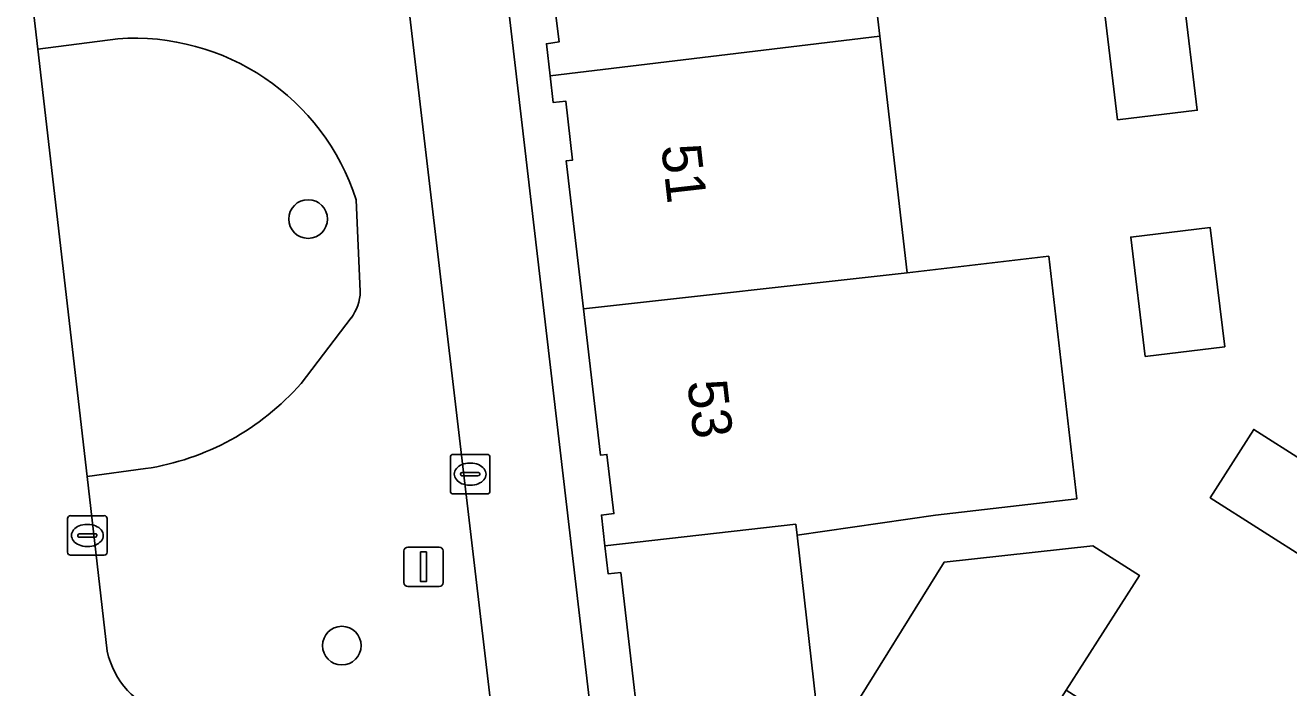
# Model space of a CAD drawing. Extents: x 160377 to 161131, y 383938 to 384853.
# Drawn here: x 160622.12 to 160654.07, y 384704.66 to 384721.42 of the extents above; entities that cross this region are included whole.
import ezdxf

# ---------------------------------------------------------------- set-up
doc = ezdxf.new("R2010")
doc.units = 0
for name, color, linetype in [('IMGEO_Boom', 7, 'Continuous'), ('IMGEO_Erf', 7, 'Continuous'), ('IMGEO_Groenvoorziening', 7, 'Continuous'), ('IMGEO_Kolk', 7, 'Continuous'), ('IMGEO_Lichtmast', 7, 'Continuous'), ('IMGEO_Pand', 7, 'Continuous'), ('IMGEO_Pand_nummerreeks', 7, 'Continuous'), ('IMGEO_Voetpad_open', 7, 'Continuous')]:
    doc.layers.add(name, color=color, linetype=linetype)

msp = doc.modelspace()

# ---------------------------------------------------------------- linework, layer by layer
at = {"layer": 'IMGEO_Boom'}
for centre in [(160629.273, 384716.516), (160630.125, 384705.727)]:
    msp.add_circle(centre, 0.489, dxfattribs=at)
at = {"layer": 'IMGEO_Erf'}
for points in [[(160632.299, 384739.297), (160636.778, 384701.013), (160651.295, 384691.787), (160664.092, 384683.65)], [(160643.028, 384727.125), (160643.724, 384721.143), (160644.42, 384715.158), (160647.997, 384715.574), (160648.71, 384709.441), (160645.133, 384709.025), (160641.634, 384708.517), (160642.115, 384704.265), (160642.853, 384703.807), (160645.353, 384707.836), (160649.116, 384708.253), (160650.289, 384707.505), (160648.439, 384704.604), (160653.696, 384701.251), (160658.7, 384698.06)], [(160637.881, 384701.541), (160637.177, 384707.576), (160636.86, 384707.539), (160636.777, 384708.248), (160636.686, 384709.028), (160637.003, 384709.065), (160636.828, 384710.561), (160636.669, 384710.542), (160636.236, 384714.242), (160635.798, 384717.99), (160635.957, 384718.008), (160635.789, 384719.496), (160635.471, 384719.46), (160635.393, 384720.133), (160635.299, 384720.95), (160635.618, 384720.995), (160635.436, 384722.483)]]:
    msp.add_lwpolyline(points, dxfattribs=at)
for points in [[(160651.751, 384719.266), (160649.737, 384719.026), (160649.375, 384722.054), (160651.39, 384722.295)], [(160652.448, 384713.287), (160650.439, 384713.042), (160650.07, 384716.058), (160652.079, 384716.303)], [(160654.625, 384707.845), (160652.082, 384709.466), (160653.183, 384711.194), (160655.726, 384709.574)]]:
    msp.add_lwpolyline(points, close=True, dxfattribs=at)
at = {"layer": 'IMGEO_Groenvoorziening'}
for points in [[(160633.874, 384704.387), (160629.795, 384739.039), (160624.35, 384738.394)], [(160624.908, 384727.058), (160621.946, 384725.035), (160622.435, 384720.808), (160624.459, 384721.074)], [(160624.459, 384721.074), (160622.435, 384720.808)], [(160622.435, 384720.808), (160623.683, 384710.004), (160625.159, 384710.204)], [(160630.592, 384714.684), (160630.487, 384717.005)], [(160630.487, 384717.005), (160630.592, 384714.684)], [(160629.094, 384712.359), (160630.357, 384714.013)], [(160630.357, 384714.013), (160629.094, 384712.359)], [(160625.159, 384710.204), (160623.683, 384710.004), (160624.193, 384705.586)]]:
    msp.add_lwpolyline(points, dxfattribs=at)
for centre, radius, start, end in [((160624.877, 384715.194), 5.895, 17.8911, 94.0689), ((160624.877, 384715.194), 5.895, 17.8911, 94.0689), ((160629.39, 384714.728), 1.203, 323.5082, 357.8889), ((160629.39, 384714.728), 1.203, 323.5082, 357.8889), ((160624.189, 384716.645), 6.514, 278.5642, 318.8504), ((160624.189, 384716.645), 6.514, 278.5642, 318.8504), ((160626.288, 384706.042), 2.144, 192.2828, 252.5189)]:
    msp.add_arc(centre, radius, start, end, dxfattribs=at)
at = {"layer": 'IMGEO_Kolk'}
for p, q in [((160632.869, 384709.638), (160632.869, 384710.49)), ((160632.944, 384710.564), (160633.796, 384710.564)), ((160633.357, 384710.344), (160633.382, 384710.344)), ((160633.87, 384710.49), (160633.87, 384709.638)), ((160633.128, 384710.058), (160633.128, 384710.07)), ((160633.566, 384710.021), (160633.168, 384710.021)), ((160633.171, 384710.107), (160633.569, 384710.107)), ((160633.612, 384710.07), (160633.612, 384710.058)), ((160633.38, 384709.784), (160633.355, 384709.784)), ((160633.796, 384709.564), (160632.944, 384709.564)), ((160623.19, 384708.088), (160623.19, 384708.94)), ((160623.265, 384709.014), (160624.117, 384709.014)), ((160623.678, 384708.794), (160623.703, 384708.794)), ((160624.191, 384708.94), (160624.191, 384708.088)), ((160623.449, 384708.508), (160623.449, 384708.52)), ((160623.887, 384708.471), (160623.489, 384708.471)), ((160623.492, 384708.557), (160623.89, 384708.557)), ((160623.933, 384708.52), (160623.933, 384708.508)), ((160623.701, 384708.234), (160623.676, 384708.234)), ((160624.117, 384708.014), (160623.265, 384708.014))]:
    msp.add_line(p, q, dxfattribs=at)
for points in [[(160632.869, 384709.638), (160632.869, 384710.49)], [(160632.944, 384710.564), (160633.796, 384710.564)], [(160633.87, 384710.49), (160633.87, 384709.638)], [(160633.796, 384709.564), (160632.944, 384709.564)], [(160623.19, 384708.088), (160623.19, 384708.94)], [(160623.265, 384709.014), (160624.117, 384709.014)], [(160624.191, 384708.94), (160624.191, 384708.088)], [(160624.117, 384708.014), (160623.265, 384708.014)]]:
    msp.add_lwpolyline(points, dxfattribs=at)
for centre, radius, start, end in [((160632.946, 384710.488), 0.0765, 91.552, 178.448), ((160632.946, 384710.488), 0.0765, 91.552, 178.448), ((160633.794, 384710.488), 0.0765, 1.552, 88.448), ((160633.794, 384710.488), 0.0765, 1.552, 88.448), ((160633.168, 384710.067), 0.0403, 85.8775, 175.7526), ((160633.165, 384710.057), 0.0366, 178.938, 274.7102), ((160633.569, 384710.064), 0.043, 264.8664, 352.4533), ((160633.573, 384710.069), 0.0386, 1.7309, 96.639), ((160632.946, 384709.64), 0.0765, 181.552, 268.448), ((160632.946, 384709.64), 0.0765, 181.552, 268.448), ((160633.794, 384709.64), 0.0765, 271.552, 358.448), ((160633.794, 384709.64), 0.0765, 271.552, 358.448), ((160623.267, 384708.938), 0.0765, 91.552, 178.448), ((160623.267, 384708.938), 0.0765, 91.552, 178.448), ((160624.115, 384708.938), 0.0765, 1.552, 88.448), ((160624.115, 384708.938), 0.0765, 1.552, 88.448), ((160623.489, 384708.517), 0.0403, 85.8775, 175.7526), ((160623.486, 384708.507), 0.0366, 178.938, 274.7102), ((160623.89, 384708.514), 0.043, 264.8664, 352.4533), ((160623.894, 384708.519), 0.0386, 1.7309, 96.639), ((160623.267, 384708.09), 0.0765, 181.552, 268.448), ((160623.267, 384708.09), 0.0765, 181.552, 268.448), ((160624.115, 384708.09), 0.0765, 271.552, 358.448), ((160624.115, 384708.09), 0.0765, 271.552, 358.448)]:
    msp.add_arc(centre, radius, start, end, dxfattribs=at)
for centre, major_axis, ratio, start_param, end_param in [((160633.356, 384710.064), (-0.387, 0.002), 0.722429, 4.712389, 7.853982), ((160633.381, 384710.064), (-0.39, 0.002), 0.717154, 1.570796, 4.712389), ((160623.677, 384708.514), (-0.387, 0.002), 0.722429, 4.712389, 7.853982), ((160623.702, 384708.514), (-0.39, 0.002), 0.717154, 1.570796, 4.712389)]:
    msp.add_ellipse(centre, major_axis=major_axis, ratio=ratio, start_param=start_param, end_param=end_param, dxfattribs=at)
at = {"layer": 'IMGEO_Lichtmast'}
for p, q in [((160631.695, 384707.321), (160631.695, 384708.121)), ((160631.695, 384708.121), (160631.695, 384707.321)), ((160631.795, 384708.221), (160632.585, 384708.221)), ((160632.585, 384708.221), (160631.795, 384708.221)), ((160632.685, 384708.121), (160632.685, 384707.321)), ((160632.685, 384707.321), (160632.685, 384708.121)), ((160632.585, 384707.221), (160631.795, 384707.221)), ((160631.795, 384707.221), (160632.585, 384707.221))]:
    msp.add_line(p, q, dxfattribs=at)
msp.add_lwpolyline([(160632.115, 384708.096), (160632.265, 384708.096), (160632.265, 384707.346), (160632.115, 384707.346), (160632.115, 384708.096)], dxfattribs=at)
for centre, start, end in [((160631.795, 384708.121), 90, 180), ((160631.795, 384708.121), 90, 180), ((160632.585, 384708.121), 0, 90), ((160632.585, 384708.121), 360, 90), ((160631.795, 384707.321), 180, 270), ((160631.795, 384707.321), 180, 270), ((160632.585, 384707.321), 270, 0), ((160632.585, 384707.321), 270, 0)]:
    msp.add_arc(centre, 0.1, start, end, dxfattribs=at)
at = {"layer": 'IMGEO_Pand'}
for points in [[(160634.846, 384726.159), (160635.277, 384722.465), (160635.436, 384722.483), (160635.618, 384720.995), (160635.299, 384720.95), (160635.393, 384720.133), (160643.724, 384721.143), (160643.028, 384727.125)], [(160651.39, 384722.295), (160649.375, 384722.054), (160649.737, 384719.026), (160651.751, 384719.266)], [(160635.393, 384720.133), (160635.471, 384719.46), (160635.789, 384719.496), (160635.957, 384718.008), (160635.798, 384717.99), (160636.236, 384714.242), (160644.42, 384715.158), (160643.724, 384721.143)], [(160652.079, 384716.303), (160650.07, 384716.058), (160650.439, 384713.042), (160652.448, 384713.287)], [(160644.42, 384715.158), (160636.236, 384714.242), (160636.669, 384710.542), (160636.828, 384710.561), (160637.003, 384709.065), (160636.686, 384709.028), (160636.777, 384708.248), (160641.602, 384708.795), (160641.634, 384708.517), (160645.133, 384709.025), (160648.71, 384709.441), (160647.997, 384715.574)], [(160653.183, 384711.194), (160652.082, 384709.466), (160654.625, 384707.845), (160655.726, 384709.574)], [(160641.602, 384708.795), (160636.777, 384708.248), (160636.86, 384707.539), (160637.177, 384707.576), (160637.881, 384701.541), (160644.014, 384697.665), (160648.439, 384704.604), (160650.289, 384707.505), (160649.116, 384708.253), (160645.353, 384707.836), (160642.853, 384703.807), (160642.115, 384704.265), (160641.634, 384708.517)]]:
    msp.add_lwpolyline(points, close=True, dxfattribs=at)
at = {"layer": 'IMGEO_Voetpad_open'}
for points in [[(160703.447, 384655.281), (160705.71, 384657.186), (160665.486, 384682.763), (160666.045, 384683.643), (160670.463, 384690.6), (160669.054, 384691.457), (160664.641, 384684.514), (160664.092, 384683.65), (160651.295, 384691.787), (160636.778, 384701.013), (160632.299, 384739.297), (160629.795, 384739.039), (160633.874, 384704.387)], [(160622.435, 384720.808), (160621.946, 384725.035), (160620.438, 384737.93), (160617.943, 384737.619), (160622.397, 384699.635), (160643.623, 384678.211), (160642.918, 384677.515), (160634.272, 384668.99), (160631.905, 384666.636), (160631.018, 384665.242), (160629.059, 384662.347), (160630.403, 384661.545), (160631.687, 384663.557), (160631.783, 384663.496), (160633.051, 384665.474), (160638.193, 384670.576), (160644.038, 384676.399), (160644.733, 384677.091), (160681.86, 384639.621), (160683.437, 384638.06), (160686.913, 384640.854)], [(160624.193, 384705.586), (160623.683, 384710.004), (160622.435, 384720.808)]]:
    msp.add_lwpolyline(points, dxfattribs=at)
msp.add_arc((160626.288, 384706.042), 2.144, 192.2828, 252.5189, dxfattribs=at)

# ---------------------------------------------------------------- texts
at = {"layer": 'IMGEO_Pand_nummerreeks'}
for s, rotation, p in [('51', 276.4642, (160638.199, 384718.359)), ('53', 276.4628, (160638.859, 384712.402))]:
    msp.add_text(s, height=1, rotation=rotation, dxfattribs=at).set_placement(p)

doc.saveas('drawing.dxf')
